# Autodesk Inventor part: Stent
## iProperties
Created: 2012-09
Part Number: Stent
Document SubType Name: Modellieren
Designer: schachinger
Mass: 0.176272 g
Surface Area: 7.05081 cm^2
Volume: 0.176272 cm^3
Density: 1 g/cm^3
Author: schachinger
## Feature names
1. Extrusion1
2. Sweeping1
3. Spiegeln1 [Mirror]
4. Runde Anordnung1 [Circular Pattern]
